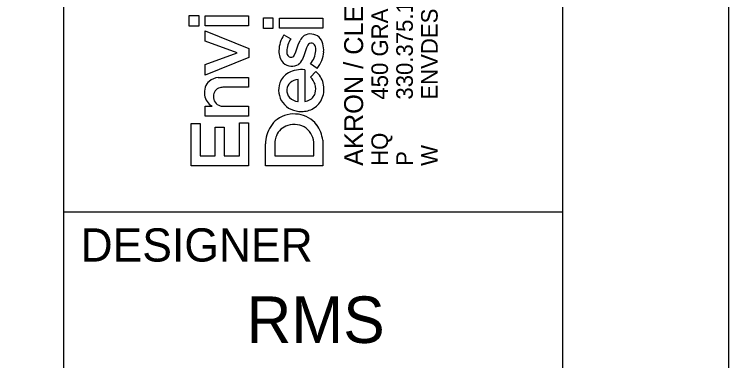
# Model space of a CAD drawing. Extents: x -0.4 to 34, y 0 to 22.
# Drawn here: x 31.851 to 34, y 2.552 to 3.594 of the extents above; entities that cross this region are included whole.
import ezdxf

# ---------------------------------------------------------------- set-up
doc = ezdxf.new("R2010")
doc.units = 0
for name, color, linetype in [('_CIVIL_CONSTRUCTION', 7, 'Continuous'), ('PF_X_Ground_Line', 7, 'Continuous'), ('UT_X_FO', 7, 'Continuous')]:
    doc.layers.add(name, color=color, linetype=linetype)

msp = doc.modelspace()

# ---------------------------------------------------------------- linework, layer by layer
at = {"layer": '_CIVIL_CONSTRUCTION'}
for p, q in [((32.3771, 3.5582), (32.3771, 3.5903)), ((32.3771, 3.5903), (32.4054, 3.5903)), ((32.4054, 3.5903), (32.4054, 3.5582)), ((32.4254, 3.5594), (32.4254, 3.5893)), ((32.4254, 3.5893), (32.5557, 3.5893)), ((32.5557, 3.5893), (32.5557, 3.5594)), ((32.6005, 3.5511), (32.6005, 3.5832)), ((32.6005, 3.5832), (32.6289, 3.5832)), ((32.6289, 3.5832), (32.6289, 3.5511)), ((32.6489, 3.5523), (32.6489, 3.5822)), ((32.6489, 3.5822), (32.7792, 3.5822)), ((32.7792, 3.5822), (32.7792, 3.5523)), ((32.4054, 3.5582), (32.3771, 3.5582)), ((32.5557, 3.5594), (32.4254, 3.5594)), ((32.6289, 3.5511), (32.6005, 3.5511)), ((32.7792, 3.5523), (32.6489, 3.5523)), ((32.4254, 3.5133), (32.4254, 3.5446)), ((32.4254, 3.5446), (32.5567, 3.4913)), ((32.6615, 3.5321), (32.6827, 3.5203)), ((32.5212, 3.478), (32.4254, 3.5133)), ((32.7048, 3.5026), (32.7104, 3.5153)), ((32.5567, 3.4913), (32.5567, 3.4644)), ((32.6967, 3.4787), (32.7048, 3.5026)), ((32.7298, 3.4933), (32.7221, 3.4688)), ((32.7334, 3.501), (32.7298, 3.4933)), ((32.4254, 3.4429), (32.5212, 3.478)), ((32.5567, 3.4644), (32.4254, 3.4109)), ((32.693, 3.4712), (32.6967, 3.4787)), ((32.7221, 3.4688), (32.7182, 3.4592)), ((32.4254, 3.4109), (32.4254, 3.4429)), ((32.7621, 3.4314), (32.742, 3.4447)), ((32.7245, 3.4275), (32.7246, 3.3319)), ((32.7423, 3.4046), (32.7577, 3.422)), ((32.4644, 3.404), (32.4729, 3.4044)), ((32.4729, 3.4044), (32.5557, 3.4044)), ((32.5557, 3.4044), (32.5557, 3.3746)), ((32.7049, 3.3318), (32.7049, 3.3983)), ((32.5557, 3.3746), (32.4814, 3.3746)), ((32.7036, 3.3317), (32.7049, 3.3318)), ((32.4254, 3.2875), (32.4254, 3.3173)), ((32.4254, 3.3173), (32.4455, 3.3173)), ((32.4822, 3.3173), (32.5557, 3.3173)), ((32.5557, 3.3173), (32.5557, 3.2876)), ((32.5557, 3.2876), (32.4254, 3.2875)), ((32.5286, 3.1683), (32.5286, 3.2672)), ((32.5286, 3.2672), (32.5557, 3.2672)), ((32.5557, 3.2672), (32.5557, 3.1379)), ((32.383, 3.1379), (32.383, 3.266)), ((32.383, 3.266), (32.4101, 3.266)), ((32.4101, 3.266), (32.4101, 3.1683)), ((32.455, 3.1683), (32.455, 3.2549)), ((32.455, 3.2549), (32.4822, 3.2549)), ((32.4822, 3.2549), (32.4822, 3.1683)), ((32.6064, 3.138), (32.6064, 3.204)), ((32.6347, 3.2118), (32.6341, 3.2023)), ((32.7785, 3.215), (32.7792, 3.2021)), ((32.6341, 3.2023), (32.6341, 3.1684)), ((32.7515, 3.1683), (32.7515, 3.2024)), ((32.7792, 3.2021), (32.7792, 3.138)), ((32.4101, 3.1683), (32.455, 3.1683)), ((32.4822, 3.1683), (32.5286, 3.1683)), ((32.6341, 3.1684), (32.7515, 3.1683)), ((32.5557, 3.1379), (32.383, 3.1379)), ((32.7792, 3.138), (32.6064, 3.138))]:
    msp.add_line(p, q, dxfattribs=at)
for points in [[(32.3771, 3.5582), (32.3771, 3.5903), (32.4054, 3.5903), (32.4054, 3.5582)], [(32.4254, 3.5594), (32.4254, 3.5893), (32.5557, 3.5893), (32.5557, 3.5594)], [(32.6005, 3.5511), (32.6005, 3.5832), (32.6289, 3.5832), (32.6289, 3.5511)], [(32.6489, 3.5523), (32.6489, 3.5822), (32.7792, 3.5822), (32.7792, 3.5523)], [(32.4254, 3.4109), (32.4254, 3.4429), (32.5212, 3.478), (32.4254, 3.5133), (32.4254, 3.5446), (32.5567, 3.4913), (32.5567, 3.4644)], [(32.383, 3.1379), (32.383, 3.266), (32.4101, 3.266), (32.4101, 3.1683), (32.455, 3.1683), (32.455, 3.2549), (32.4822, 3.2549), (32.4822, 3.1683), (32.5286, 3.1683), (32.5286, 3.2672), (32.5557, 3.2672), (32.5557, 3.1379)]]:
    msp.add_lwpolyline(points, close=True, dxfattribs=at)
for points in [[(32.6615, 3.5321), (32.6827, 3.5203)], [(32.693, 3.4712), (32.6967, 3.4787), (32.7048, 3.5026), (32.7104, 3.5153)], [(32.7334, 3.501), (32.7298, 3.4933), (32.7221, 3.4688), (32.7182, 3.4592)], [(32.7621, 3.4314), (32.742, 3.4447)], [(32.7245, 3.4275), (32.7246, 3.3319)], [(32.7423, 3.4046), (32.7577, 3.422)], [(32.4644, 3.404), (32.4729, 3.4044), (32.5557, 3.4044), (32.5557, 3.3746), (32.4814, 3.3746)], [(32.7036, 3.3317), (32.7049, 3.3318), (32.7049, 3.3983)], [(32.4254, 3.2875), (32.4254, 3.3173), (32.4455, 3.3173)], [(32.4822, 3.3173), (32.5557, 3.3173), (32.5557, 3.2876), (32.4254, 3.2875)], [(32.7785, 3.215), (32.7792, 3.2021), (32.7792, 3.138), (32.6064, 3.138)], [(32.6064, 3.138), (32.6064, 3.204)], [(32.6347, 3.2118), (32.6341, 3.2023), (32.6341, 3.1684), (32.7515, 3.1683), (32.7515, 3.2024)]]:
    msp.add_lwpolyline(points, dxfattribs=at)
for centre, radius, start, end in [((32.7364, 3.4826), 0.0897, 146.531, 178.7571), ((32.7364, 3.4826), 0.0897, 146.531, 178.7571), ((32.7466, 3.4971), 0.0405, 125.5118, 153.4159), ((32.7466, 3.4971), 0.0405, 125.5118, 153.4159), ((32.7406, 3.5026), 0.0326, 80.1719, 122.5197), ((32.7406, 3.5026), 0.0326, 80.1719, 122.5197), ((32.7428, 3.4982), 0.0367, 47.7934, 84.6892), ((32.7428, 3.4982), 0.0367, 47.7934, 84.6892), ((32.7379, 3.4946), 0.0427, 14.9966, 46.2063), ((32.7379, 3.4946), 0.0427, 14.9966, 46.2063), ((32.7452, 3.4789), 0.0749, 146.5112, 176.9101), ((32.7452, 3.4789), 0.0749, 146.5112, 176.9101), ((32.7438, 3.4963), 0.0114, 76.6609, 155.7053), ((32.7438, 3.4963), 0.0114, 76.6609, 155.7053), ((32.744, 3.4951), 0.0126, 21.5098, 78.5262), ((32.744, 3.4951), 0.0126, 21.5098, 78.5262), ((32.7104, 3.4867), 0.0712, 355.8306, 15.3914), ((32.7104, 3.4867), 0.0712, 355.8306, 15.3914), ((32.6967, 3.4824), 0.0501, 177.5366, 222.7932), ((32.6967, 3.4824), 0.0501, 177.5366, 222.7932), ((32.6931, 3.4823), 0.0228, 178.4747, 211.0868), ((32.6931, 3.4823), 0.0228, 178.4747, 211.0868), ((32.6825, 3.4915), 0.0757, 321.811, 354.7969), ((32.6825, 3.4915), 0.0757, 321.811, 354.7969), ((32.7259, 3.4877), 0.0321, 354.5726, 22.068), ((32.7259, 3.4877), 0.0321, 354.5726, 22.068), ((32.6833, 3.4767), 0.0115, 212.2368, 268.3777), ((32.6833, 3.4767), 0.0115, 212.2368, 268.3777), ((32.6834, 3.4759), 0.0107, 267.716, 333.7337), ((32.6834, 3.4759), 0.0107, 267.716, 333.7337), ((32.6895, 3.4882), 0.0922, 321.9777, 355.8738), ((32.6895, 3.4882), 0.0922, 321.9777, 355.8738), ((32.686, 3.4753), 0.0375, 225.9854, 302.4797), ((32.686, 3.4753), 0.0375, 225.9854, 302.4797), ((32.681, 3.4758), 0.0408, 308.0877, 335.9874), ((32.681, 3.4758), 0.0408, 308.0877, 335.9874), ((32.7024, 3.3691), 0.0558, 118.8308, 160.6244), ((32.7024, 3.3691), 0.0558, 118.8308, 160.6244), ((32.7152, 3.3441), 0.0838, 83.615, 118.2876), ((32.7152, 3.3441), 0.0838, 83.615, 118.2876), ((32.7174, 3.3717), 0.0644, 13.5336, 51.3615), ((32.7174, 3.3717), 0.0644, 13.5336, 51.3615), ((32.4687, 3.3543), 0.0499, 94.9696, 130.2225), ((32.4687, 3.3543), 0.0499, 94.9696, 130.2225), ((32.7079, 3.3561), 0.0424, 94.008, 130.8817), ((32.7079, 3.3561), 0.0424, 94.008, 130.8817), ((32.7038, 3.3656), 0.0549, 19.0357, 45.4406), ((32.7038, 3.3656), 0.0549, 19.0357, 45.4406), ((32.4787, 3.3582), 0.056, 162.2736, 187.7919), ((32.4787, 3.3582), 0.056, 162.2736, 187.7919), ((32.4635, 3.3626), 0.0402, 132.2219, 161.6818), ((32.4635, 3.3626), 0.0402, 132.2219, 161.6818), ((32.4811, 3.3286), 0.046, 89.6049, 105.3284), ((32.4811, 3.3286), 0.046, 89.6049, 105.3284), ((32.7104, 3.3661), 0.0644, 160.5201, 215.7831), ((32.7104, 3.3661), 0.0644, 160.5201, 215.7831), ((32.7005, 3.3663), 0.0298, 132.9851, 177.179), ((32.7005, 3.3663), 0.0298, 132.9851, 177.179), ((32.7107, 3.3697), 0.047, 344.6059, 17.007), ((32.7107, 3.3697), 0.047, 344.6059, 17.007), ((32.7064, 3.3692), 0.0758, 339.3542, 13.3785), ((32.7064, 3.3692), 0.0758, 339.3542, 13.3785), ((32.4748, 3.3487), 0.025, 103.6865, 182.2187), ((32.4748, 3.3487), 0.025, 103.6865, 182.2187), ((32.7017, 3.365), 0.0311, 175.0013, 223.283), ((32.7017, 3.365), 0.0311, 175.0013, 223.283), ((32.7224, 3.3671), 0.035, 288.0077, 343.5508), ((32.7224, 3.3671), 0.035, 288.0077, 343.5508), ((32.4703, 3.358), 0.0476, 188.962, 238.7037), ((32.4703, 3.358), 0.0476, 188.962, 238.7037), ((32.4773, 3.3456), 0.0276, 175.5854, 255.1439), ((32.4773, 3.3456), 0.0276, 175.5854, 255.1439), ((32.7089, 3.3736), 0.0423, 225.0619, 262.7974), ((32.7089, 3.3736), 0.0423, 225.0619, 262.7974), ((32.7247, 3.3522), 0.0202, 269.7003, 294.8711), ((32.7247, 3.3522), 0.0202, 269.7003, 294.8711), ((32.7189, 3.3652), 0.0626, 300.9427, 338.7323), ((32.7189, 3.3652), 0.0626, 300.9427, 338.7323), ((32.4818, 3.3595), 0.0422, 254.0916, 270.5284), ((32.4818, 3.3595), 0.0422, 254.0916, 270.5284), ((32.7125, 3.3705), 0.0687, 217.7452, 271.6543), ((32.7125, 3.3705), 0.0687, 217.7452, 271.6543), ((32.7155, 3.3724), 0.0706, 269.2048, 300.3341), ((32.7155, 3.3724), 0.0706, 269.2048, 300.3341), ((32.6923, 3.2079), 0.0864, 81.194, 125.9984), ((32.6923, 3.2079), 0.0864, 81.194, 125.9984), ((32.6946, 3.2113), 0.0827, 37.8521, 82.402), ((32.6946, 3.2113), 0.0827, 37.8521, 82.402), ((32.6939, 3.2089), 0.0865, 127.2362, 165.148), ((32.6939, 3.2089), 0.0865, 127.2362, 165.148), ((32.6889, 3.2078), 0.054, 106.1881, 157.3861), ((32.6889, 3.2078), 0.054, 106.1881, 157.3861), ((32.6928, 3.1986), 0.0639, 55.6727, 107.2093), ((32.6928, 3.1986), 0.0639, 55.6727, 107.2093), ((32.6929, 3.205), 0.0587, 357.4662, 52.2665), ((32.6929, 3.205), 0.0587, 357.4662, 52.2665), ((32.6859, 3.2057), 0.0931, 5.7333, 37.304), ((32.6859, 3.2057), 0.0931, 5.7333, 37.304), ((32.7143, 3.2028), 0.1078, 164.7861, 179.3704), ((32.7143, 3.2028), 0.1078, 164.7861, 179.3704), ((32.6983, 3.2039), 0.0641, 157.3571, 172.9275), ((32.6983, 3.2039), 0.0641, 157.3571, 172.9275)]:
    msp.add_arc(centre, radius, start, end, dxfattribs=at)
at = {"layer": 'PF_X_Ground_Line'}
for p, q in [((32, 0.5), (32, 21.5)), ((32, 3), (33.5, 3))]:
    msp.add_line(p, q, dxfattribs=at)
msp.add_lwpolyline([(1.5, 21.5), (33.5, 21.5), (33.5, 0.5), (1.5, 0.5)], close=True, dxfattribs=at)
at = {"layer": 'UT_X_FO'}
msp.add_lwpolyline([(0, 0), (34, 0), (34, 22), (0, 22)], close=True, dxfattribs=at)

# ---------------------------------------------------------------- texts
at = {"layer": '_CIVIL_CONSTRUCTION'}
for s, height, p in [('450 GRANT ST., AKRON, OH  44311', 0.049846, (32.9749, 3.3374)), ('AKRON / CLEVELAND / COLUMBUS', 0.056969, (32.9001, 3.138)), ('ENVDESIGNGROUP.COM', 0.049846, (33.1244, 3.3374)), ('330.375.1390', 0.049846, (33.0497, 3.3374)), ('HQ ', 0.04985, (32.9749, 3.138)), ('W', 0.0498, (33.1244, 3.138)), ('P', 0.0498, (33.0497, 3.138))]:
    msp.add_text(s, height=height, rotation=90, dxfattribs=at).set_placement(p)
for s, height, p in [('DESIGNER', 0.1, (32.05, 2.85)), ('RMS', 0.14, (32.5491, 2.605))]:
    msp.add_text(s, height=height, dxfattribs=at).set_placement(p)

doc.saveas('drawing.dxf')
